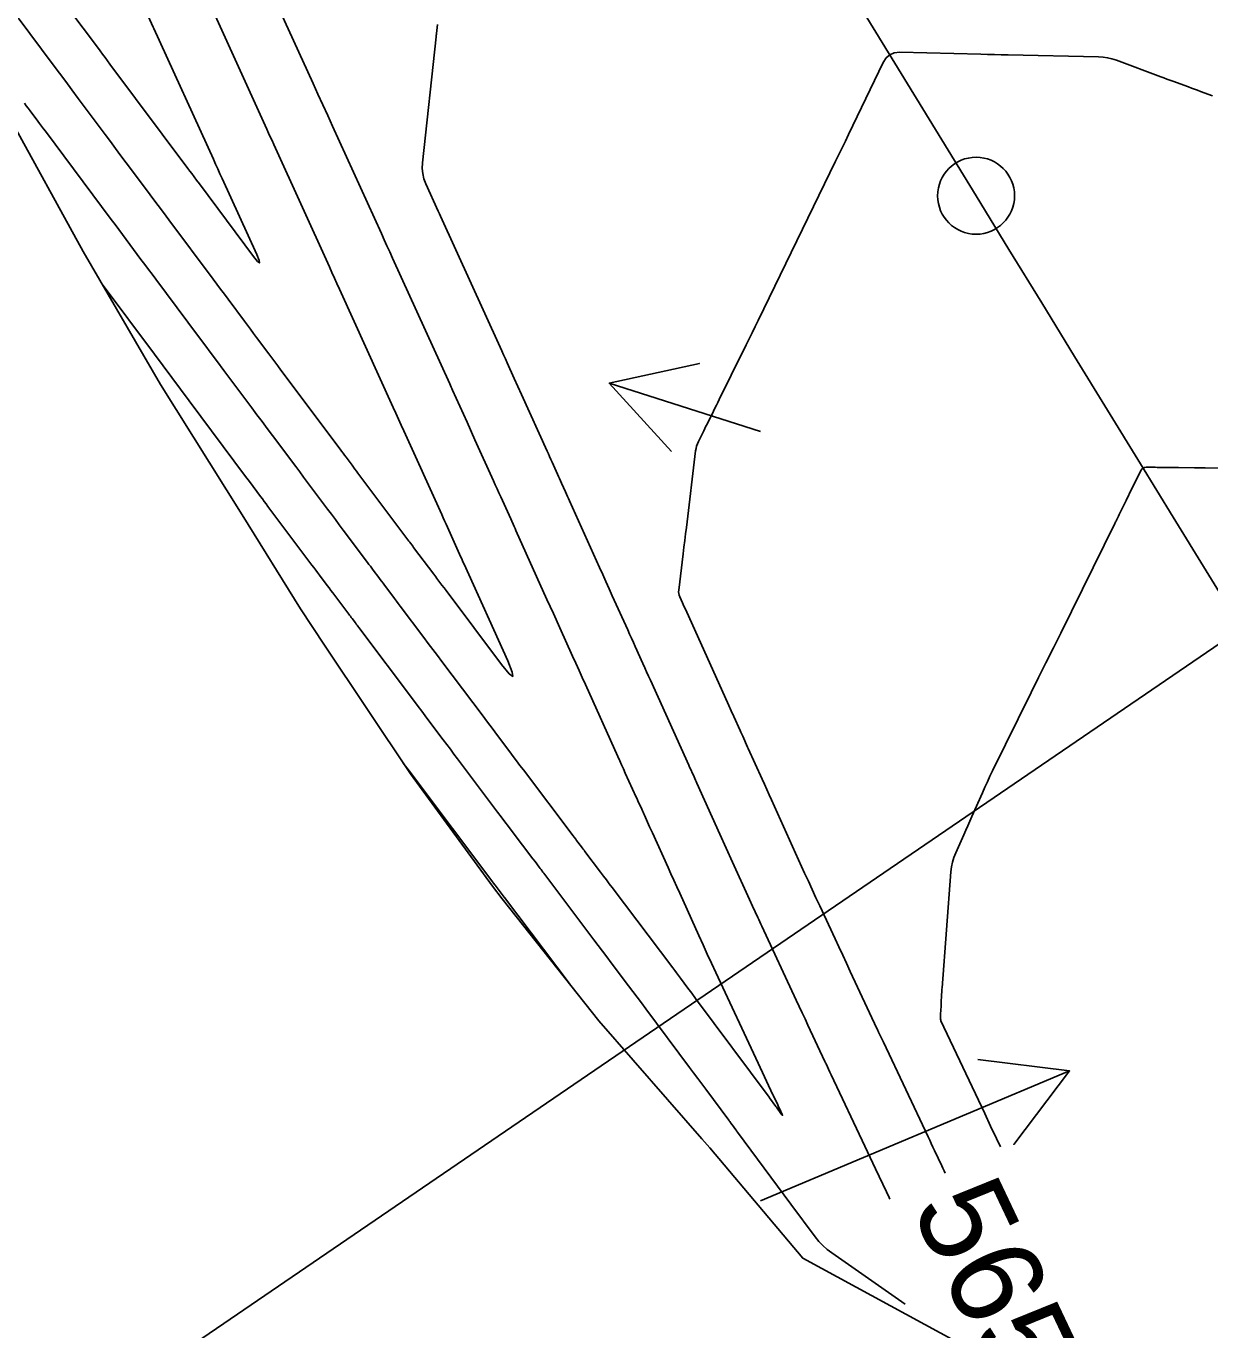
# Model space of a CAD drawing. Extents: x 954385 to 988206, y 1868364 to 1924553.
# Drawn here: x 957159.4 to 957236.3, y 1920710.5 to 1920795.3 of the extents above; entities that cross this region are included whole.
import ezdxf

# ---------------------------------------------------------------- set-up
doc = ezdxf.new("R2010")
doc.units = 0
for name, color, linetype in [('21', 7, 'Continuous'), ('24', 7, 'Continuous'), ('26', 7, 'Continuous'), ('5', 7, 'Continuous'), ('6', 7, 'Continuous'), ('7', 7, 'Continuous'), ('Default', 7, 'Continuous')]:
    doc.layers.add(name, color=color, linetype=linetype)

msp = doc.modelspace()

# ---------------------------------------------------------------- linework, layer by layer
at = {"layer": '21'}
msp.add_circle((957221.14, 1920784.239), 2.5, dxfattribs=at)
at = {"layer": '24'}
msp.add_lwpolyline([(957220.044, 1920709.686), (957209.88, 1920715.201), (957203.844, 1920722.364), (957203.326, 1920722.955), (957196.631, 1920730.624), (957190.358, 1920738.556), (957189.726, 1920739.365), (957184.387, 1920746.677), (957178.815, 1920755.042), (957177.254, 1920757.387), (957173.459, 1920763.504), (957168.141, 1920771.973), (957163.121, 1920780.625), (957158.307, 1920789.403)], dxfattribs=at)
at = {"layer": '26'}
for points in [[(957207.131, 1920768.928), (957197.304, 1920772.068), (957203.167, 1920773.344), (957197.304, 1920772.068), (957201.341, 1920767.629)], [(957257.131, 1920768.928), (957121.717, 1920676.45), (957124.316, 1920681.858), (957121.717, 1920676.45), (957127.7, 1920676.903)], [(957207.131, 1920718.928), (957227.216, 1920727.371), (957223.589, 1920722.592), (957227.216, 1920727.371), (957221.264, 1920728.123)]]:
    msp.add_lwpolyline(points, dxfattribs=at)
at = {"layer": '6'}
for points in [[(957219.134, 1920720.733), (957219.066, 1920720.879), (957218.987, 1920721.045), (957218.909, 1920721.211), (957218.44, 1920722.204), (957218.336, 1920722.425), (957218.232, 1920722.646), (957218.127, 1920722.867), (957218.023, 1920723.088), (957215.118, 1920729.242), (957215.103, 1920729.272), (957215.089, 1920729.303), (957215.074, 1920729.334), (957215.059, 1920729.365), (957214.808, 1920729.892), (957214.781, 1920729.949), (957214.755, 1920730.006), (957214.728, 1920730.063), (957214.701, 1920730.12), (957212.969, 1920733.835), (957212.72, 1920734.367), (957212.472, 1920734.899), (957212.224, 1920735.431), (957211.976, 1920735.963), (957210.983, 1920738.092), (957210.736, 1920738.624), (957210.49, 1920739.158), (957210.245, 1920739.691), (957210.002, 1920740.226), (957207.85, 1920744.982), (957207.697, 1920745.32), (957207.544, 1920745.659), (957207.39, 1920745.997), (957207.237, 1920746.335), (957206.342, 1920748.312), (957206.294, 1920748.418), (957205.976, 1920749.12), (957205.935, 1920749.21), (957205.895, 1920749.3), (957205.854, 1920749.391), (957205.813, 1920749.481), (957205.4, 1920750.395), (957205.236, 1920750.76), (957205.071, 1920751.125), (957202.251, 1920757.376), (957202.16, 1920757.578), (957202.068, 1920757.781), (957201.885, 1920758.187), (957201.847, 1920758.289), (957201.823, 1920758.394), (957201.815, 1920758.501), (957201.821, 1920758.611), (957202.107, 1920760.97), (957202.159, 1920761.4), (957202.212, 1920761.83), (957202.264, 1920762.26), (957202.316, 1920762.69), (957202.919, 1920767.659), (957202.945, 1920767.815), (957202.983, 1920767.967), (957203.034, 1920768.115), (957203.098, 1920768.26), (957203.379, 1920768.83), (957203.449, 1920768.972), (957203.52, 1920769.115), (957203.59, 1920769.257), (957203.661, 1920769.399), (957204.079, 1920770.246), (957204.173, 1920770.435), (957204.266, 1920770.623), (957204.359, 1920770.812), (957204.453, 1920771.001), (957204.845, 1920771.795), (957204.941, 1920771.99), (957205.038, 1920772.185), (957205.134, 1920772.38), (957205.231, 1920772.575), (957206.207, 1920774.551), (957206.401, 1920774.946), (957206.595, 1920775.341), (957206.788, 1920775.736), (957206.981, 1920776.132), (957212.011, 1920786.478), (957212.223, 1920786.915), (957212.434, 1920787.352), (957212.646, 1920787.79), (957212.856, 1920788.228), (957215.097, 1920792.9), (957215.287, 1920793.197), (957215.531, 1920793.406), (957215.828, 1920793.528), (957216.179, 1920793.562), (957221.44, 1920793.429), (957221.885, 1920793.418), (957222.33, 1920793.407), (957222.776, 1920793.397), (957223.221, 1920793.388), (957229.088, 1920793.27), (957229.386, 1920793.252), (957229.68, 1920793.208), (957229.969, 1920793.14), (957230.253, 1920793.047), (957233.133, 1920791.968), (957233.332, 1920791.894), (957233.53, 1920791.821), (957233.729, 1920791.747), (957233.927, 1920791.675), (957234.939, 1920791.306), (957235.133, 1920791.235), (957235.328, 1920791.163), (957235.523, 1920791.092), (957235.718, 1920791.021), (957236.498, 1920790.737)], [(957194.757, 1920732.993), (957190.499, 1920738.637), (957190.481, 1920738.661), (957189.893, 1920739.441), (957189.772, 1920739.602), (957189.745, 1920739.638), (957184.435, 1920746.692), (957184.391, 1920746.751), (957183.923, 1920747.374)]]:
    msp.add_lwpolyline(points, dxfattribs=at)
at = {"layer": '7'}
for points in [[(957159.083, 1920800.544), (957163.12, 1920795.135), (957163.596, 1920794.497), (957164.231, 1920793.647), (957164.39, 1920793.434), (957164.549, 1920793.221), (957164.707, 1920793.009), (957164.866, 1920792.796), (957169.93, 1920786.008), (957170.055, 1920785.841), (957170.179, 1920785.674), (957170.491, 1920785.256), (957170.678, 1920785.005), (957174.195, 1920780.294), (957174.459, 1920779.965), (957174.581, 1920779.876), (957174.562, 1920780.026), (957174.401, 1920780.416), (957172.158, 1920785.352), (957172.016, 1920785.666), (957171.873, 1920785.979), (957171.73, 1920786.293), (957171.588, 1920786.607), (957167.724, 1920795.101), (957167.679, 1920795.2), (957163.801, 1920803.734)], [(957159.307, 1920790.256), (957159.43, 1920790.09), (957159.554, 1920789.924), (957159.678, 1920789.758), (957160.174, 1920789.094), (957160.298, 1920788.928), (957160.421, 1920788.762), (957160.545, 1920788.596), (957160.669, 1920788.43), (957164.954, 1920782.688), (957165.195, 1920782.365), (957165.436, 1920782.042), (957165.678, 1920781.718), (957165.919, 1920781.395), (957166.883, 1920780.103), (957167.124, 1920779.78), (957167.366, 1920779.457), (957167.607, 1920779.134), (957167.848, 1920778.811), (957170.615, 1920775.101), (957171.029, 1920774.547), (957171.442, 1920773.993), (957171.856, 1920773.439), (957172.27, 1920772.885), (957174.077, 1920770.464), (957174.415, 1920770.013), (957174.752, 1920769.561), (957175.09, 1920769.109), (957175.427, 1920768.657), (957176.937, 1920766.635), (957177.195, 1920766.291), (957177.452, 1920765.947), (957177.709, 1920765.603), (957177.967, 1920765.259), (957178.996, 1920763.883), (957179.254, 1920763.539), (957179.511, 1920763.195), (957179.769, 1920762.851), (957180.026, 1920762.507), (957181.602, 1920760.403), (957181.693, 1920760.281), (957181.785, 1920760.159), (957181.876, 1920760.038), (957181.967, 1920759.916), (957182.333, 1920759.429), (957182.425, 1920759.308), (957182.516, 1920759.186), (957182.607, 1920759.064), (957182.699, 1920758.943), (957183.24, 1920758.221), (957183.361, 1920758.06), (957183.482, 1920757.899), (957183.602, 1920757.739), (957183.723, 1920757.578), (957185.256, 1920755.539), (957185.552, 1920755.146), (957185.847, 1920754.753), (957186.143, 1920754.359), (957186.439, 1920753.966), (957189.105, 1920750.419), (957189.323, 1920750.128), (957189.541, 1920749.838), (957189.76, 1920749.548), (957189.978, 1920749.257), (957190.852, 1920748.096), (957191.07, 1920747.806), (957191.289, 1920747.516), (957191.507, 1920747.226), (957191.726, 1920746.936), (957194.954, 1920742.653), (957195.031, 1920742.551), (957195.128, 1920742.423), (957195.185, 1920742.346), (957195.493, 1920741.937), (957195.551, 1920741.86), (957195.609, 1920741.783), (957195.667, 1920741.706), (957195.724, 1920741.63), (957196.74, 1920740.283), (957196.929, 1920740.034), (957197.117, 1920739.784), (957197.306, 1920739.534), (957197.495, 1920739.284), (957201.435, 1920734.064), (957201.559, 1920733.899), (957201.683, 1920733.735), (957201.806, 1920733.57), (957201.929, 1920733.405), (957202.42, 1920732.745), (957202.666, 1920732.414), (957202.911, 1920732.084), (957207.693, 1920725.655), (957207.71, 1920725.632), (957208.136, 1920725.051), (957208.165, 1920725.012), (957208.251, 1920724.895), (957208.527, 1920724.523), (957208.556, 1920724.487), (957208.569, 1920724.476), (957208.567, 1920724.493), (957208.548, 1920724.535), (957208.363, 1920724.928), (957208.308, 1920725.044), (957208.28, 1920725.102), (957208.253, 1920725.16), (957207.976, 1920725.742), (957207.949, 1920725.798), (957207.939, 1920725.819), (957206.976, 1920727.885), (957204.231, 1920733.768), (957203.954, 1920734.365), (957203.678, 1920734.963), (957203.404, 1920735.561), (957203.132, 1920736.16), (957201.883, 1920738.919), (957201.693, 1920739.338), (957201.504, 1920739.757), (957201.314, 1920740.176), (957201.125, 1920740.594), (957200.108, 1920742.841), (957199.927, 1920743.242), (957199.59, 1920743.984), (957199.547, 1920744.08), (957199.503, 1920744.177), (957199.46, 1920744.273), (957199.416, 1920744.369), (957199.164, 1920744.924), (957199.135, 1920744.987), (957199.088, 1920745.091), (957199.06, 1920745.154), (957198.351, 1920746.724), (957198.23, 1920746.992), (957198.109, 1920747.261), (957197.988, 1920747.53), (957197.866, 1920747.798), (957195.757, 1920752.472), (957195.549, 1920752.933), (957195.341, 1920753.395), (957195.132, 1920753.857), (957194.924, 1920754.318), (957194.091, 1920756.165), (957193.675, 1920757.089), (957193.258, 1920758.012), (957191.239, 1920762.49), (957191.183, 1920762.614), (957191.127, 1920762.739), (957190.902, 1920763.237), (957190.254, 1920764.676), (957190.136, 1920764.937), (957190.019, 1920765.197), (957189.901, 1920765.458), (957189.784, 1920765.718), (957188.584, 1920768.37), (957188.066, 1920769.516), (957187.12, 1920771.607), (957187.075, 1920771.707), (957187.03, 1920771.807), (957186.984, 1920771.907), (957186.939, 1920772.007), (957183.226, 1920780.187), (957183.045, 1920780.585), (957182.865, 1920780.982), (957182.685, 1920781.379), (957182.504, 1920781.777), (957179.327, 1920788.769), (957179.012, 1920789.462), (957178.697, 1920790.155), (957178.382, 1920790.848), (957178.067, 1920791.541), (957174.938, 1920798.419)], [(957171.589, 1920796.193), (957175.062, 1920788.557), (957175.174, 1920788.312), (957175.285, 1920788.067), (957175.396, 1920787.823), (957175.507, 1920787.578), (957179.124, 1920779.618), (957179.289, 1920779.256), (957179.453, 1920778.894), (957179.617, 1920778.532), (957179.782, 1920778.171), (957183.271, 1920770.482), (957183.445, 1920770.101), (957183.618, 1920769.719), (957183.791, 1920769.337), (957183.963, 1920768.955), (957186.419, 1920763.526), (957186.513, 1920763.318), (957186.607, 1920763.11), (957186.701, 1920762.902), (957186.794, 1920762.695), (957187.668, 1920760.756), (957187.72, 1920760.641), (957187.772, 1920760.526), (957187.823, 1920760.41), (957187.875, 1920760.295), (957190.71, 1920754.009), (957191.006, 1920753.285), (957191.039, 1920753.004), (957190.809, 1920753.168), (957190.316, 1920753.776), (957186.705, 1920758.581), (957186.572, 1920758.758), (957186.439, 1920758.935), (957186.173, 1920759.289), (957186.107, 1920759.377), (957186.04, 1920759.466), (957185.974, 1920759.554), (957185.907, 1920759.643), (957184.595, 1920761.391), (957184.545, 1920761.458), (957184.495, 1920761.525), (957184.394, 1920761.659), (957184.344, 1920761.725), (957184.294, 1920761.792), (957180.981, 1920766.217), (957180.884, 1920766.347), (957180.787, 1920766.476), (957180.69, 1920766.606), (957180.593, 1920766.735), (957180.205, 1920767.253), (957180.108, 1920767.383), (957180.011, 1920767.512), (957179.914, 1920767.642), (957179.817, 1920767.772), (957175.976, 1920772.914), (957175.779, 1920773.179), (957175.581, 1920773.443), (957175.384, 1920773.708), (957175.186, 1920773.972), (957174.396, 1920775.03), (957174.199, 1920775.294), (957174.002, 1920775.559), (957173.804, 1920775.823), (957173.607, 1920776.087), (957172.542, 1920777.514), (957172.299, 1920777.84), (957172.056, 1920778.166), (957171.813, 1920778.492), (957171.569, 1920778.818), (957168.684, 1920782.683), (957168.34, 1920783.145), (957167.995, 1920783.607), (957167.65, 1920784.069), (957167.306, 1920784.53), (957165.927, 1920786.378), (957165.583, 1920786.839), (957165.238, 1920787.301), (957164.893, 1920787.763), (957164.549, 1920788.225), (957162.802, 1920790.567), (957162.396, 1920791.112), (957161.99, 1920791.656), (957161.583, 1920792.2), (957161.177, 1920792.744), (957158.898, 1920795.797)], [(957186.141, 1920795.356), (957186.079, 1920794.774), (957186.074, 1920794.719), (957186.068, 1920794.665), (957186.062, 1920794.611), (957186.056, 1920794.556), (957185.176, 1920786.368), (957185.161, 1920786.018), (957185.192, 1920785.675), (957185.27, 1920785.34), (957185.394, 1920785.013), (957186.201, 1920783.237), (957186.277, 1920783.069), (957186.353, 1920782.902), (957190.209, 1920774.407), (957190.325, 1920774.151), (957190.442, 1920773.894), (957190.558, 1920773.638), (957190.674, 1920773.381), (957191.138, 1920772.355), (957191.37, 1920771.842), (957191.602, 1920771.328), (957193.27, 1920767.642), (957193.35, 1920767.464), (957193.431, 1920767.285), (957193.511, 1920767.107), (957193.592, 1920766.928), (957193.944, 1920766.145), (957194.009, 1920766.001), (957194.074, 1920765.857), (957194.139, 1920765.712), (957194.204, 1920765.568), (957194.464, 1920764.991), (957194.529, 1920764.847), (957194.594, 1920764.703), (957194.659, 1920764.558), (957194.724, 1920764.414), (957196.676, 1920760.085), (957196.884, 1920759.625), (957197.091, 1920759.165), (957197.298, 1920758.706), (957197.506, 1920758.246), (957198.504, 1920756.033), (957198.627, 1920755.76), (957198.75, 1920755.486), (957198.874, 1920755.213), (957198.997, 1920754.94), (957199.49, 1920753.847), (957199.613, 1920753.573), (957199.737, 1920753.3), (957199.86, 1920753.027), (957199.983, 1920752.754), (957202.474, 1920747.235), (957202.499, 1920747.178), (957202.817, 1920746.477), (957202.864, 1920746.374), (957202.91, 1920746.271), (957202.957, 1920746.169), (957203.003, 1920746.066), (957204.499, 1920742.762), (957204.91, 1920741.853), (957205.322, 1920740.944), (957206.424, 1920738.509), (957206.621, 1920738.074), (957206.949, 1920737.349), (957207.015, 1920737.204), (957207.081, 1920737.059), (957207.148, 1920736.915), (957207.215, 1920736.77), (957209.458, 1920731.962), (957209.647, 1920731.556), (957209.836, 1920731.151), (957210.025, 1920730.745), (957210.214, 1920730.339), (957211.312, 1920727.988), (957211.331, 1920727.946), (957211.35, 1920727.905), (957211.37, 1920727.864), (957211.389, 1920727.823), (957211.64, 1920727.297), (957211.662, 1920727.25), (957211.684, 1920727.203), (957211.707, 1920727.156), (957211.729, 1920727.11), (957213.913, 1920722.481), (957214.088, 1920722.111), (957214.263, 1920721.74), (957214.438, 1920721.37), (957214.613, 1920720.999), (957215.313, 1920719.517), (957215.488, 1920719.146), (957215.541, 1920719.033)], [(957216.532, 1920712.206), (957211.758, 1920715.545), (957211.459, 1920715.773), (957211.18, 1920716.022), (957210.923, 1920716.293), (957210.687, 1920716.587), (957209.111, 1920718.715), (957205.649, 1920723.387), (957205.626, 1920723.418), (957205.603, 1920723.45), (957205.58, 1920723.481), (957205.557, 1920723.512), (957205.466, 1920723.636), (957205.42, 1920723.699), (957205.374, 1920723.761), (957205.211, 1920723.981), (957205.177, 1920724.028), (957205.142, 1920724.075), (957205.107, 1920724.122), (957205.072, 1920724.169), (957203.574, 1920726.183), (957203.313, 1920726.535), (957203.052, 1920726.886), (957202.79, 1920727.237), (957202.529, 1920727.588), (957199.687, 1920731.41), (957199.407, 1920731.786), (957199.126, 1920732.161), (957198.845, 1920732.535), (957198.564, 1920732.909), (957197.435, 1920734.403), (957197.153, 1920734.777), (957196.871, 1920735.151), (957196.589, 1920735.524), (957196.307, 1920735.898), (957193.112, 1920740.133), (957193.052, 1920740.212), (957192.993, 1920740.291), (957192.875, 1920740.448), (957192.815, 1920740.527), (957192.756, 1920740.606), (957192.483, 1920740.968), (957192.341, 1920741.156), (957191.007, 1920742.927), (957190.768, 1920743.243), (957190.53, 1920743.559), (957190.292, 1920743.875), (957190.054, 1920744.192), (957187.45, 1920747.651), (957187.217, 1920747.961), (957186.985, 1920748.27), (957186.752, 1920748.58), (957186.519, 1920748.889), (957185.588, 1920750.128), (957185.356, 1920750.437), (957185.123, 1920750.747), (957184.89, 1920751.056), (957184.658, 1920751.366), (957181.032, 1920756.188), (957180.978, 1920756.26), (957180.923, 1920756.333), (957180.869, 1920756.405), (957180.814, 1920756.478), (957180.596, 1920756.769), (957180.541, 1920756.841), (957180.487, 1920756.914), (957180.432, 1920756.987), (957180.378, 1920757.059), (957179.473, 1920758.263), (957179.349, 1920758.428), (957179.225, 1920758.593), (957179.101, 1920758.758), (957178.978, 1920758.923), (957178.483, 1920759.583), (957178.36, 1920759.749), (957178.236, 1920759.914), (957178.112, 1920760.079), (957177.989, 1920760.244), (957175.135, 1920764.057), (957175.014, 1920764.219), (957174.892, 1920764.381), (957174.771, 1920764.543), (957174.65, 1920764.705), (957174.165, 1920765.354), (957173.923, 1920765.678), (957173.681, 1920766.003), (957170.015, 1920770.912), (957169.449, 1920771.669), (957168.883, 1920772.427), (957168.318, 1920773.185), (957167.752, 1920773.943), (957164.36, 1920778.49)], [(957222.727, 1920722.434), (957222.468, 1920722.982), (957222.087, 1920723.788), (957221.707, 1920724.594), (957218.86, 1920730.628), (957218.84, 1920730.678), (957218.826, 1920730.729), (957218.82, 1920730.782), (957218.82, 1920730.835), (957218.836, 1920731.108), (957218.846, 1920731.271), (957218.867, 1920731.613), (957218.869, 1920731.636), (957218.87, 1920731.658), (957218.874, 1920731.748), (957218.9, 1920732.358), (957218.905, 1920732.464), (957218.911, 1920732.569), (957218.918, 1920732.675), (957218.926, 1920732.78), (957219.507, 1920740.312), (957219.545, 1920740.629), (957219.609, 1920740.939), (957219.7, 1920741.243), (957219.817, 1920741.541), (957220.337, 1920742.717), (957220.467, 1920743.011), (957220.598, 1920743.305), (957220.728, 1920743.599), (957220.858, 1920743.893), (957221.549, 1920745.449), (957221.709, 1920745.805), (957221.873, 1920746.16), (957222.041, 1920746.513), (957222.212, 1920746.864), (957224.727, 1920751.961), (957225.204, 1920752.927), (957225.681, 1920753.893), (957226.159, 1920754.859), (957226.636, 1920755.825), (957230.154, 1920762.942), (957230.18, 1920762.994), (957230.206, 1920763.047), (957230.231, 1920763.099), (957230.257, 1920763.152), (957230.385, 1920763.414), (957230.436, 1920763.519), (957230.462, 1920763.572), (957230.88, 1920764.429), (957230.959, 1920764.589), (957231.038, 1920764.75), (957231.116, 1920764.91), (957231.196, 1920765.07), (957231.85, 1920766.389), (957231.911, 1920766.481), (957231.987, 1920766.547), (957232.08, 1920766.585), (957232.19, 1920766.598), (957232.66, 1920766.593), (957232.778, 1920766.592), (957232.895, 1920766.591), (957233.013, 1920766.59), (957233.13, 1920766.589), (957233.738, 1920766.584), (957233.879, 1920766.583), (957234.019, 1920766.582), (957234.159, 1920766.58), (957234.3, 1920766.578), (957235.331, 1920766.563), (957235.447, 1920766.561), (957235.564, 1920766.56), (957235.797, 1920766.557), (957235.856, 1920766.556), (957235.914, 1920766.555), (957235.972, 1920766.555), (957236.031, 1920766.554), (957240.646, 1920766.513)]]:
    msp.add_lwpolyline(points, dxfattribs=at)
at = {"layer": 'Default'}
msp.add_line((957221.14, 1920784.239), (956045.796, 1922705.182), dxfattribs=at)
msp.add_arc((966995.782, 1926764.927), 11459.156, 211.4606918, 214.0750737, dxfattribs=at)

# ---------------------------------------------------------------- texts
at = {"layer": '5'}
msp.add_text('565', height=6, rotation=295.32794, dxfattribs=at).set_placement((957216.881, 1920718.482))

doc.saveas('drawing.dxf')
